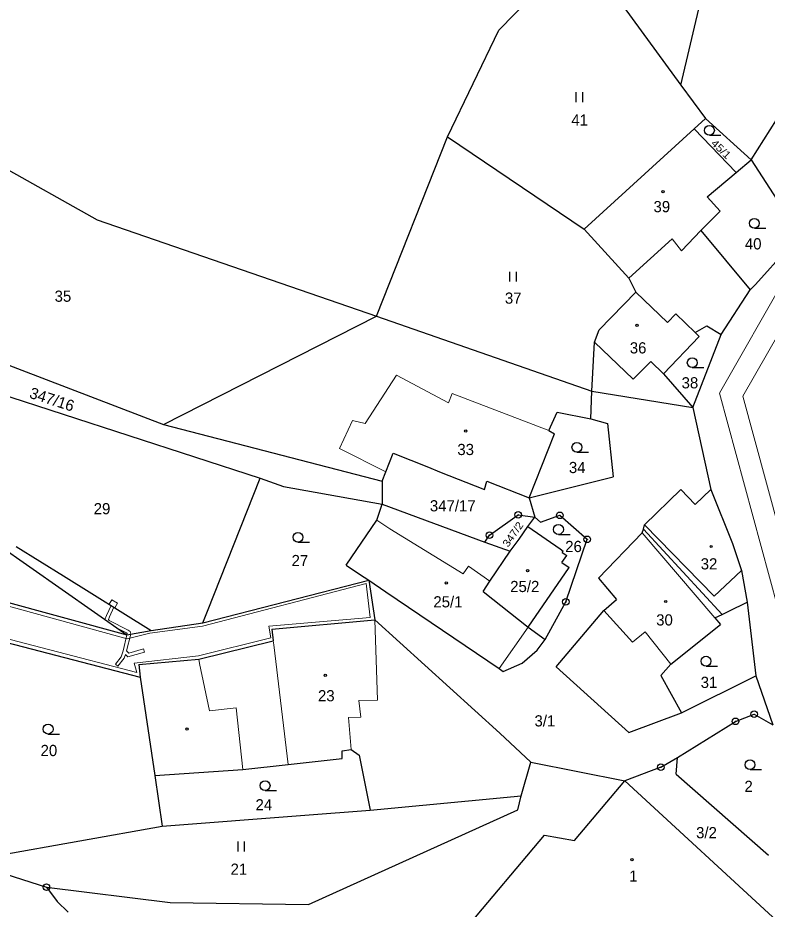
# Model space of a CAD drawing. Extents: x -633485 to -630509, y -1112692 to -1108818.
# Drawn here: x -632090.4 to -631976.6, y -1111853.5 to -1111718.1 of the extents above; entities that cross this region are included whole.
import ezdxf

# ---------------------------------------------------------------- set-up
doc = ezdxf.new("R2010")
doc.units = 0
doc.header["$LTSCALE"] = 0.68
for name, color, linetype, lineweight in [('1', 7, 'Continuous', 25), ('13', 7, 'Continuous', 13), ('3', 7, 'Continuous', 25), ('4', 7, 'Continuous', 13), ('5', 7, 'Continuous', 25), ('8', 7, 'Continuous', 25)]:
    doc.layers.add(name, color=color, linetype=linetype, lineweight=lineweight)
doc.layers.add('2', color=7, linetype='Continuous')

msp = doc.modelspace()

# ---------------------------------------------------------------- linework, layer by layer
at = {"layer": '1'}
for p, q in [((-631989.69, -1111728.27), (-631981.02, -1111691.61)), ((-632017.35, -1111719.93), (-632005.02, -1111707.28)), ((-632005.02, -1111707.28), (-631989.69, -1111728.27)), ((-632025.12, -1111736.15), (-632017.35, -1111719.93)), ((-631989.69, -1111728.27), (-631985.96, -1111733.37)), ((-631978.99, -1111739.63), (-631974.18, -1111732.05)), ((-631987.67, -1111734.93), (-631985.96, -1111733.37)), ((-631985.96, -1111733.37), (-631978.99, -1111739.63)), ((-632004.38, -1111750.18), (-631987.67, -1111734.93)), ((-631987.67, -1111734.93), (-631981.27, -1111741.57)), ((-632035.93, -1111763.38), (-632025.12, -1111736.15)), ((-632025.12, -1111736.15), (-632004.38, -1111750.18)), ((-632098.05, -1111737.68), (-632078.38, -1111748.73)), ((-631981.27, -1111741.57), (-631978.99, -1111739.63)), ((-631978.99, -1111739.63), (-631971.65, -1111751.05)), ((-631985.68, -1111745.27), (-631981.27, -1111741.57)), ((-631985.68, -1111745.27), (-631983.7, -1111747.42)), ((-631986.65, -1111750.37), (-631983.7, -1111747.42)), ((-632078.38, -1111748.73), (-632035.93, -1111763.38)), ((-632004.38, -1111750.18), (-631997.6, -1111757.62)), ((-631986.65, -1111750.37), (-631979.18, -1111759.37)), ((-631978.36, -1111758.59), (-631971.65, -1111751.05)), ((-631997.6, -1111757.62), (-631996.51, -1111759.72)), ((-631983.59, -1111766.18), (-631979.18, -1111759.37)), ((-631979.18, -1111759.37), (-631978.36, -1111758.59)), ((-632002.09, -1111765.49), (-631996.51, -1111759.72)), ((-631996.51, -1111759.72), (-631991.71, -1111764.36)), ((-632068.27, -1111779.85), (-632035.93, -1111763.38)), ((-632035.93, -1111763.38), (-632003.22, -1111774.81)), ((-631991.71, -1111764.36), (-631990.45, -1111763.05)), ((-631990.45, -1111763.05), (-631987.51, -1111765.89)), ((-632002.79, -1111767.35), (-632002.09, -1111765.49)), ((-631987.51, -1111765.89), (-631985.74, -1111764.86)), ((-631987.51, -1111765.89), (-631986.92, -1111766.46)), ((-631985.74, -1111764.86), (-631983.59, -1111766.18)), ((-632003.22, -1111774.81), (-632002.79, -1111767.35)), ((-631992.33, -1111772.14), (-631986.92, -1111766.46)), ((-631987.85, -1111777.26), (-631983.59, -1111766.18)), ((-632096.75, -1111768.94), (-632068.27, -1111779.85)), ((-632100.47, -1111772.77), (-632053.61, -1111788.03)), ((-631992.33, -1111772.14), (-631987.85, -1111777.26)), ((-632003.38, -1111778.99), (-632003.22, -1111774.81)), ((-632003.22, -1111774.81), (-631987.85, -1111777.26)), ((-632009.75, -1111780.78), (-632008.47, -1111777.97)), ((-632008.47, -1111777.97), (-632003.38, -1111778.99)), ((-631987.85, -1111777.26), (-631985.15, -1111789.75)), ((-632003.38, -1111778.99), (-632000.84, -1111779.7)), ((-632000.84, -1111779.7), (-632000, -1111787.82)), ((-632068.27, -1111779.85), (-632035.07, -1111788.45)), ((-632009.75, -1111780.78), (-632008.87, -1111781.27)), ((-632012.76, -1111790.98), (-632008.87, -1111781.27)), ((-632112.13, -1111784.99), (-632073.84, -1111811.83)), ((-632034.51, -1111787.06), (-632033.39, -1111784.23)), ((-632033.39, -1111784.23), (-632028.04, -1111786.36)), ((-632028.04, -1111786.36), (-632026.36, -1111787.02)), ((-632035.07, -1111788.45), (-632034.51, -1111787.06)), ((-632026.36, -1111787.02), (-632019.5, -1111789.74)), ((-632012.76, -1111790.98), (-632000, -1111787.82)), ((-632061.59, -1111808.22), (-632053.61, -1111788.03)), ((-632053.61, -1111788.03), (-632050.06, -1111789.29)), ((-632035.07, -1111788.45), (-632035.05, -1111791.98)), ((-632019.5, -1111789.74), (-632019.17, -1111788.44)), ((-632019.17, -1111788.44), (-632012.76, -1111790.98)), ((-632050.06, -1111789.29), (-632035.05, -1111791.98)), ((-631995.2, -1111795.12), (-631989.7, -1111789.74)), ((-631989.7, -1111789.74), (-631987.54, -1111792.01)), ((-631987.54, -1111792.01), (-631985.15, -1111789.75)), ((-631985.15, -1111789.75), (-631981.84, -1111797.92)), ((-632012.76, -1111790.98), (-632011.88, -1111793.93)), ((-632035.89, -1111794.37), (-632035.05, -1111791.98)), ((-632035.05, -1111791.98), (-632019.48, -1111797.71)), ((-632040.52, -1111801.24), (-632035.89, -1111794.37)), ((-632018.77, -1111796.66), (-632014.4, -1111793.58)), ((-632014.4, -1111793.58), (-632011.88, -1111793.93)), ((-632012.93, -1111795.33), (-632011.88, -1111793.93)), ((-632011.88, -1111793.93), (-632011.02, -1111794.67)), ((-632011.02, -1111794.67), (-632008.09, -1111793.65)), ((-632008.09, -1111793.65), (-632003.91, -1111797.3)), ((-632014.27, -1111797.3), (-632012.93, -1111795.33)), ((-632012.93, -1111795.33), (-632008.05, -1111798.73)), ((-631995.57, -1111796.31), (-631995.37, -1111795.76)), ((-631995.37, -1111795.76), (-631995.2, -1111795.12)), ((-631995.37, -1111795.76), (-631983.43, -1111808.71)), ((-632019.48, -1111797.71), (-632018.77, -1111796.66)), ((-632015.63, -1111799.12), (-632014.27, -1111797.3)), ((-632007.15, -1111806.81), (-632003.91, -1111797.3)), ((-632002.22, -1111803.19), (-631995.57, -1111796.31)), ((-632090.65, -1111798.4), (-632083.46, -1111802.85)), ((-632019.48, -1111797.71), (-632015.63, -1111799.12)), ((-631981.84, -1111797.92), (-631980.46, -1111802.02)), ((-632121.12, -1111798.87), (-632073.84, -1111811.83)), ((-632018.69, -1111803.65), (-632015.63, -1111799.12)), ((-632008.05, -1111798.73), (-632007.55, -1111799.08)), ((-632007.75, -1111800.81), (-632007.01, -1111799.75)), ((-632007.7, -1111799.28), (-632007.55, -1111799.08)), ((-632007.7, -1111799.28), (-632007.01, -1111799.75)), ((-632040.52, -1111801.24), (-632038.51, -1111802.59)), ((-632007.75, -1111800.81), (-632006.67, -1111801.57)), ((-632038.51, -1111802.59), (-632037.11, -1111803.53)), ((-632012.91, -1111810.63), (-632006.67, -1111801.57)), ((-631980.46, -1111802.02), (-631979.6, -1111806.87)), ((-632083.46, -1111802.85), (-632070.17, -1111811.13)), ((-632062.31, -1111810.01), (-632037.11, -1111803.53)), ((-632037.11, -1111803.53), (-632036.16, -1111809.51)), ((-632037.11, -1111803.53), (-632034.5, -1111805.3)), ((-632019.75, -1111805.22), (-632018.69, -1111803.65)), ((-632002.22, -1111803.19), (-631999.48, -1111806.42)), ((-632034.5, -1111805.3), (-632017.3, -1111816.92)), ((-632019.75, -1111805.22), (-632012.91, -1111810.63)), ((-632001.37, -1111808.13), (-631999.48, -1111806.42)), ((-632010.31, -1111812.51), (-632007.15, -1111806.81)), ((-632008.61, -1111816.7), (-632001.37, -1111808.13)), ((-631982.42, -1111808.23), (-631979.6, -1111806.87)), ((-631979.6, -1111806.87), (-631978.28, -1111818.02)), ((-632062.31, -1111810.01), (-632061.59, -1111808.22)), ((-632051.84, -1111810.94), (-632036.16, -1111809.51)), ((-632036.16, -1111809.51), (-632017.19, -1111826.73)), ((-631984.53, -1111809.24), (-631983.43, -1111808.71)), ((-631984.53, -1111809.24), (-631983.67, -1111810.24)), ((-631983.43, -1111808.71), (-631982.42, -1111808.23)), ((-632070.17, -1111811.13), (-632062.31, -1111810.01)), ((-632012.91, -1111810.63), (-632010.31, -1111812.51)), ((-631991.22, -1111816.28), (-631983.67, -1111810.24)), ((-632099.14, -1111811.2), (-632071.85, -1111818.23)), ((-632073.84, -1111811.83), (-632070.17, -1111811.13)), ((-632051.84, -1111810.94), (-632051.62, -1111812.7)), ((-632062.94, -1111815.49), (-632051.62, -1111812.7)), ((-632011.52, -1111814.12), (-632010.31, -1111812.51)), ((-632013.82, -1111816.13), (-632011.52, -1111814.12)), ((-632072.03, -1111816.33), (-632062.94, -1111815.49)), ((-632016.67, -1111817.37), (-632013.82, -1111816.13)), ((-631992.72, -1111818), (-631991.22, -1111816.28)), ((-632072.03, -1111816.33), (-632071.85, -1111818.23)), ((-632017.3, -1111816.92), (-632016.67, -1111817.37)), ((-632008.61, -1111816.7), (-631997.58, -1111826.66)), ((-632071.85, -1111818.23), (-632069.61, -1111833.21)), ((-631992.72, -1111818), (-631989.58, -1111823.64)), ((-631989.58, -1111823.64), (-631978.28, -1111818.02)), ((-631978.28, -1111818.02), (-631975.72, -1111825.48)), ((-631997.58, -1111826.66), (-631989.58, -1111823.64)), ((-631981.39, -1111824.96), (-631978.57, -1111823.88)), ((-631978.57, -1111823.88), (-631975.72, -1111825.48)), ((-631990.19, -1111830.47), (-631981.39, -1111824.96)), ((-632017.19, -1111826.73), (-632012.5, -1111831.16)), ((-632041.13, -1111830.62), (-632041.12, -1111829.42)), ((-632041.12, -1111829.42), (-632039.78, -1111829.23)), ((-632039.78, -1111829.23), (-632038.56, -1111830.11)), ((-632049.36, -1111831.53), (-632041.13, -1111830.62)), ((-632038.56, -1111830.11), (-632036.89, -1111838.48)), ((-632013.96, -1111836.29), (-632012.5, -1111831.16)), ((-632012.5, -1111831.16), (-631998.22, -1111834.02)), ((-631992.74, -1111831.93), (-631990.19, -1111830.47)), ((-631990.41, -1111832.98), (-631990.19, -1111830.47)), ((-632069.61, -1111833.21), (-632056.22, -1111832.28)), ((-632056.22, -1111832.28), (-632049.36, -1111831.53)), ((-631992.74, -1111831.93), (-631998.22, -1111834.02)), ((-632069.61, -1111833.21), (-632068.47, -1111840.91)), ((-631990.41, -1111832.98), (-631976.39, -1111845.3)), ((-632005.85, -1111843.04), (-631998.22, -1111834.02)), ((-631998.22, -1111834.02), (-631974.46, -1111855.89)), ((-632036.89, -1111838.48), (-632013.96, -1111836.29)), ((-632014.46, -1111838.39), (-632013.96, -1111836.29)), ((-632068.47, -1111840.91), (-632046.81, -1111839.21)), ((-632046.81, -1111839.21), (-632036.89, -1111838.48)), ((-632046.28, -1111852.79), (-632014.46, -1111838.39)), ((-632098.38, -1111846.22), (-632068.47, -1111840.91)), ((-632030.12, -1111865.6), (-632010.39, -1111842.25)), ((-632010.39, -1111842.25), (-632005.85, -1111843.04)), ((-632098.38, -1111846.22), (-632086.08, -1111850.17)), ((-632086.08, -1111850.17), (-632084.43, -1111852.32)), ((-632086.08, -1111850.17), (-632067.28, -1111852.48)), ((-632084.43, -1111852.32), (-632082.76, -1111853.97)), ((-632067.28, -1111852.48), (-632046.28, -1111852.79))]:
    msp.add_line(p, q, dxfattribs=at)
at = {"layer": '13'}
for points in [[(-631916.51, -1111708.73), (-631937.96, -1111724.98), (-631973.62, -1111757.27), (-631983.84, -1111775.09), (-631973.7, -1111812.39), (-631964.38, -1111846.95), (-631945.65, -1111913.51)], [(-631942.03, -1111914.22), (-631961.2, -1111846.09), (-631970.19, -1111812.76), (-631968.28, -1111811.65), (-631968.99, -1111808.24), (-631971.08, -1111809.45), (-631980.3, -1111775.55), (-631971.02, -1111759.37), (-631935.9, -1111727.56), (-631914.51, -1111711.36)]]:
    msp.add_lwpolyline(points, dxfattribs=at)
for points in [[(-632073.33, -1111811.33), (-632073.64, -1111811.1), (-632076.53, -1111809.62), (-632076.63, -1111809.46), (-632076.5, -1111809.06), (-632075.83, -1111807.6), (-632075.7, -1111807.69), (-632075.28, -1111807.01), (-632076.13, -1111806.48), (-632076.55, -1111807.16), (-632076.25, -1111807.34), (-632076.96, -1111808.86), (-632077.18, -1111809.49), (-632075.32, -1111810.8), (-632073.9, -1111811.52), (-632073.79, -1111811.61), (-632073.84, -1111811.83), (-632073.27, -1111811.72)], [(-632074.25, -1111815.38), (-632074.05, -1111814.81), (-632073.69, -1111815.16), (-632071.16, -1111814.43), (-632071.3, -1111813.95), (-632073.55, -1111814.6), (-632073.89, -1111814.26), (-632073.27, -1111811.72), (-632073.84, -1111811.83), (-632074.4, -1111814.26), (-632074.71, -1111815.16), (-632075.6, -1111816.26), (-632075.21, -1111816.57)]]:
    msp.add_lwpolyline(points, close=True, dxfattribs=at)
at = {"layer": '3'}
for p, q in [((-632005.581, -1111730.86), (-632005.581, -1111729.36)), ((-632004.58, -1111730.86), (-632004.58, -1111729.36)), ((-631985.353, -1111735.91), (-631983.603, -1111735.91)), ((-631978.523, -1111750.03), (-631976.773, -1111750.03)), ((-632015.681, -1111758.13), (-632015.681, -1111756.63)), ((-632014.68, -1111758.13), (-632014.68, -1111756.63)), ((-631987.963, -1111771.21), (-631986.213, -1111771.21)), ((-632005.483, -1111784.07), (-632003.733, -1111784.07)), ((-632008.283, -1111796.55), (-632006.533, -1111796.55)), ((-632047.863, -1111797.74), (-632046.113, -1111797.74)), ((-631985.873, -1111816.57), (-631984.123, -1111816.57)), ((-632085.813, -1111826.89), (-632084.063, -1111826.89)), ((-631979.183, -1111832.3), (-631977.433, -1111832.3)), ((-632052.853, -1111835.48), (-632051.103, -1111835.48)), ((-632056.961, -1111844.73), (-632056.961, -1111843.23)), ((-632055.96, -1111844.73), (-632055.96, -1111843.23))]:
    msp.add_line(p, q, dxfattribs=at)
for centre in [(-631985.3529, -1111735.1598), (-631978.5229, -1111749.2798), (-631987.9629, -1111770.4598), (-632005.4829, -1111783.3198), (-632008.2829, -1111795.7998), (-632047.8629, -1111796.9898), (-631985.8729, -1111815.8198), (-632085.8129, -1111826.1398), (-631979.1829, -1111831.5498), (-632052.8529, -1111834.7298)]:
    msp.add_circle(centre, 0.75, dxfattribs=at)
at = {"layer": '4'}
for p, q in [((-631989.61, -1111753.44), (-631986.65, -1111750.37)), ((-631997.6, -1111757.62), (-631991.03, -1111751.63)), ((-631991.03, -1111751.63), (-631989.61, -1111753.44)), ((-632002.79, -1111767.35), (-631996.95, -1111772.96)), ((-631996.95, -1111772.96), (-631994.26, -1111770.28)), ((-631994.26, -1111770.28), (-631992.33, -1111772.14)), ((-632037.65, -1111779.7), (-632032.89, -1111772.37)), ((-632032.89, -1111772.37), (-632024.98, -1111776.58)), ((-632024.98, -1111776.58), (-632024.43, -1111775.16)), ((-632024.43, -1111775.16), (-632009.75, -1111780.78)), ((-632041.57, -1111783.49), (-632039.57, -1111779.22)), ((-632039.57, -1111779.22), (-632037.65, -1111779.7)), ((-632041.57, -1111783.49), (-632034.51, -1111787.06)), ((-632035.89, -1111794.37), (-632033.88, -1111795.73)), ((-632033.88, -1111795.73), (-632022.76, -1111802.54)), ((-631995.2, -1111795.12), (-631984.61, -1111805.92)), ((-631995.57, -1111796.31), (-631984.53, -1111809.24)), ((-632022.76, -1111802.54), (-632021.96, -1111801.39)), ((-632021.96, -1111801.39), (-632018.69, -1111803.65)), ((-631984.61, -1111805.92), (-631980.46, -1111802.02)), ((-632001.37, -1111808.13), (-631997.05, -1111812.92)), ((-632036.16, -1111809.51), (-632035.79, -1111821.75)), ((-632017.3, -1111816.92), (-632012.91, -1111810.63)), ((-631997.05, -1111812.92), (-631995.13, -1111811.38)), ((-631995.13, -1111811.38), (-631991.22, -1111816.28)), ((-632051.62, -1111812.7), (-632051.55, -1111813.33)), ((-632051.55, -1111813.33), (-632049.36, -1111831.53)), ((-632062.94, -1111815.49), (-632062.8, -1111816.16)), ((-632062.8, -1111816.16), (-632061.28, -1111823.34)), ((-632061.28, -1111823.34), (-632057.24, -1111822.9)), ((-632057.24, -1111822.9), (-632056.22, -1111832.28)), ((-632038.6, -1111821.78), (-632035.79, -1111821.75)), ((-632038.6, -1111821.78), (-632038.31, -1111824.34)), ((-632040.18, -1111824.36), (-632038.31, -1111824.34)), ((-632040.18, -1111824.36), (-632039.78, -1111829.23))]:
    msp.add_line(p, q, dxfattribs=at)
for points in [[(-632189.94, -1111779.63), (-632171.73, -1111788.1), (-632150.63, -1111796.76), (-632133.35, -1111803.2), (-632116.61, -1111806.57), (-632106.56, -1111808.49), (-632098.83, -1111810.64), (-632072.34, -1111817.55), (-632072.75, -1111816.1), (-632062.98, -1111814.99), (-632051.99, -1111812.26), (-632052.29, -1111810.51)], [(-632052.29, -1111810.51), (-632036.9, -1111809.18), (-632037.48, -1111804), (-632062.36, -1111810.51), (-632070.38, -1111811.56), (-632073.81, -1111812.43), (-632121.32, -1111799.36)]]:
    msp.add_lwpolyline(points, dxfattribs=at)
at = {"layer": '5'}
for centre in [(-631992.3968, -1111744.4792), (-631996.3368, -1111764.7692), (-632022.3768, -1111780.8592), (-631985.0868, -1111798.3892), (-632012.9668, -1111802.0692), (-632025.3268, -1111803.9192), (-631991.9968, -1111806.7492), (-632043.7068, -1111817.9492), (-632064.6968, -1111826.1292), (-631997.1168, -1111845.9892)]:
    msp.add_circle(centre, 0.175, dxfattribs=at)
at = {"layer": '8'}
for centre, radius in [((-632014.4, -1111793.5799), 0.5), ((-632008.09, -1111793.6499), 0.5), ((-632014.4, -1111793.5799), 0.0303), ((-632008.09, -1111793.6499), 0.0303), ((-632018.77, -1111796.6599), 0.5), ((-632018.77, -1111796.6599), 0.0303), ((-632003.91, -1111797.2999), 0.5), ((-632003.91, -1111797.2999), 0.0303), ((-632007.15, -1111806.8099), 0.5), ((-632007.15, -1111806.8099), 0.0303), ((-631978.57, -1111823.8799), 0.5), ((-631978.57, -1111823.8799), 0.0303), ((-631981.39, -1111824.9599), 0.5), ((-631981.39, -1111824.9599), 0.0303), ((-631992.74, -1111831.9299), 0.5), ((-631992.74, -1111831.9299), 0.0303), ((-632086.08, -1111850.1699), 0.5), ((-632086.08, -1111850.1699), 0.0303)]:
    msp.add_circle(centre, radius, dxfattribs=at)

# ---------------------------------------------------------------- texts
at = {"layer": '2'}
for s, p in [('41', (-632006.33, -1111734.425)), ('39', (-631993.85, -1111747.595)), ('40', (-631979.97, -1111753.245)), ('35', (-632084.83, -1111761.205)), ('37', (-632016.42, -1111761.495)), ('36', (-631997.45, -1111769.055)), ('38', (-631989.58, -1111774.365)), ('33', (-632023.65, -1111784.495)), ('34', (-632006.7, -1111787.235)), ('29', (-632078.89, -1111793.495)), ('347/17', (-632027.82, -1111793.055)), ('26', (-632007.26, -1111799.235)), ('27', (-632048.83, -1111801.375)), ('32', (-631986.68, -1111801.875)), ('25/2', (-632015.62, -1111805.315)), ('25/1', (-632027.29, -1111807.645)), ('30', (-631993.44, -1111810.395)), ('31', (-631986.68, -1111819.885)), ('23', (-632044.82, -1111821.915)), ('3/1', (-632011.93, -1111825.735)), ('20', (-632086.96, -1111830.235)), ('2', (-631980.03, -1111835.685)), ('24', (-632054.31, -1111838.485)), ('3/2', (-631987.38, -1111842.725)), ('21', (-632058.1, -1111848.275)), ('1', (-631997.54, -1111849.325))]:
    msp.add_text(s, height=1.7, dxfattribs=at).set_placement(p)
for s, rotation, width, p in [('45/1', 316, 1.15, (-631985.207, -1111737.234)), ('347/2', 55, 1.1, (-632015.936, -1111798.583))]:
    msp.add_text(s, height=1.139, rotation=rotation, dxfattribs=dict(at, width=width)).set_placement(p)
msp.add_text('347/16', height=1.7, rotation=342, dxfattribs=at).set_placement((-632088.791, -1111775.764))

doc.saveas('drawing.dxf')
